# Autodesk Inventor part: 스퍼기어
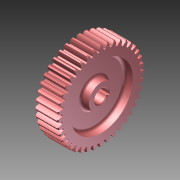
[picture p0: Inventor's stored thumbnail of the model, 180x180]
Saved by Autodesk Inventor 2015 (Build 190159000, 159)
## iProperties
Created: 2024-12
Part Number: 스퍼기어
Material: 일반
Document SubType Name: Modeling
Designer: 10401
Density: 1 g/cm^3
Appearance: 기본값
Author: 10401
Author: jhkim
Creation Date: 2024-11-28
Sending System: Autodesk Inventor 2025
Preprocessor: ST-DEVELOPER v20
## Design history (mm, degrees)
node "스퍼기어1"
node "솔리드1"
node "기준1"
